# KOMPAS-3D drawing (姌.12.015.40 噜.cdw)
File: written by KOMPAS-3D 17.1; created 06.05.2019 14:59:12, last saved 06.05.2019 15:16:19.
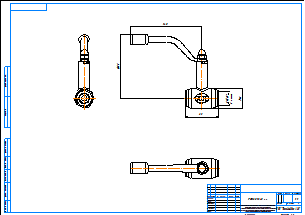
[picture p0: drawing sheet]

Sheet 1: A2, landscape

Title block, sheet 1: name: КШ.12.015.40 рр; material: Внимание! Данный продукт является объектом авторского права ООО «Торговый Дом АДЛ». / Запрещается изменение, копирование, распространение / (в том числе путем копирования на другие сайты и ресурсы в Интернете) / или любое иное использование информации и объектов без предварительного / согласия правообладателя (ООО «Торговый Дом АДЛ»).; scale: 1:1; sheets: 1; organisation: ООО "Торговый дом АДЛ"; sheet format: A2; stored path: C:\Users\tra\Desktop\2д чертежи\Шаровые краны БИВАЛ\КШ_Бивал_серия_11_12\KOMPAS_2D\КШ.12.015.40 рр.cdw

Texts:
  user
Dimensions and other numbers on the sheet: 65; 125,5; 1/2; 2 места; 38; 140; 1:1; 1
